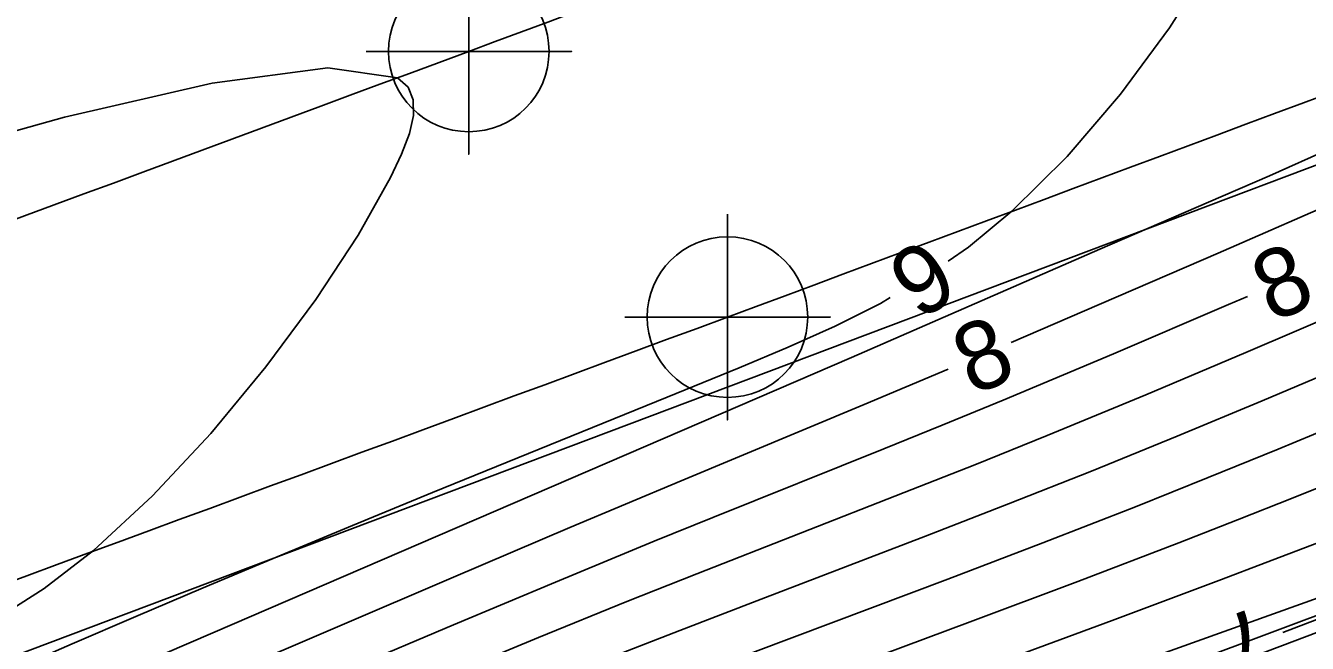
# Model space of a CAD drawing. Extents: x 2602990 to 2605851, y 618069 to 619180.
# Drawn here: x 2603377.87 to 2603415.29, y 618421.79 to 618439.82 of the extents above; entities that cross this region are included whole.
import ezdxf

# ---------------------------------------------------------------- set-up
doc = ezdxf.new("R2010")
doc.units = 0
for name, color, linetype in [('DTM Contours Major', 7, 'Continuous'), ('DTM Contours Major Text', 7, 'Continuous'), ('DTM Contours Minor', 7, 'Continuous'), ('DTM Contours Minor Text', 7, 'Continuous'), ('Exist DTM Breakline', 7, 'Continuous'), ('Exist DTM Crownline', 7, 'Continuous'), ('Exist DTM Crownline Cogo Point CELL', 7, 'Continuous'), ('Exist DTM Drainline', 7, 'Continuous'), ('Exist Roads EOP', 7, 'Continuous'), ('Exist Roads EOP Cogo Point CELL', 7, 'Continuous')]:
    doc.layers.add(name, color=color, linetype=linetype)

# ---------------------------------------------------------------- blocks, each defined once
blk = doc.blocks.new('EXIST DTM CROWNLINE COGO POINT')
at = {"layer": 'Exist DTM Crownline Cogo Point CELL'}
blk.add_lwpolyline([(0, 0.06), (0, -0.06), (0, 0), (0.06, 0), (-0.06, 0)], dxfattribs=at)
blk.add_circle((0, 0), 0.04688, dxfattribs=at)
blk = doc.blocks.new('EXIST ROADS EOP COGO POINT')
at = {"layer": 'Exist Roads EOP Cogo Point CELL'}
blk.add_lwpolyline([(0, 0.06), (0, -0.06), (0, 0), (0.06, 0), (-0.06, 0)], dxfattribs=at)
blk.add_circle((0, 0), 0.04688, dxfattribs=at)

msp = doc.modelspace()

# ---------------------------------------------------------------- linework, layer by layer
at = {"layer": 'DTM Contours Major'}
msp.add_lwpolyline([(2603413.545, 618431.919), (2603412.996, 618431.681), (2603409.631, 618430.243), (2603406.411, 618428.892), (2603404.635, 618428.163), (2603402.929, 618427.472), (2603397.939, 618425.471), (2603396.224, 618424.775), (2603393.341, 618423.584), (2603390.362, 618422.333), (2603387.382, 618421.067), (2603378.36, 618417.204), (2603374.888, 618415.735), (2603371.983, 618414.523), (2603369.421, 618413.467), (2603366.184, 618412.15), (2603362.493, 618410.666), (2603360.498, 618409.871), (2603355.313, 618407.823), (2603347.349, 618404.69), (2603343.063, 618402.99), (2603334.617, 618399.609), (2603327.541, 618396.809), (2603322.626, 618394.861)], dxfattribs=at)
at = {"layer": 'DTM Contours Minor'}
for points in [[(2603412.497, 618441.689), (2603411.27, 618439.754), (2603409.841, 618437.822), (2603408.283, 618436.003), (2603406.67, 618434.405), (2603405.399, 618433.355), (2603404.81, 618432.947)], [(2603374.173, 618435.798), (2603379.013, 618437.147), (2603383.32, 618438.14), (2603386.693, 618438.587), (2603388.731, 618438.3), (2603389.043, 618438.023), (2603389.193, 618437.655), (2603389.198, 618437.203), (2603389.078, 618436.671), (2603388.849, 618436.066), (2603388.529, 618435.392), (2603387.578, 618433.71), (2603386.342, 618431.832), (2603384.886, 618429.866), (2603383.277, 618427.918), (2603381.579, 618426.096), (2603379.858, 618424.507), (2603378.413, 618423.398), (2603377, 618422.497)], [(2603415.971, 618436.239), (2603414.184, 618435.441), (2603412.408, 618434.669), (2603410.673, 618433.922), (2603409.232, 618433.298), (2603401.988, 618430.14), (2603383.339, 618422.102), (2603375.419, 618418.701), (2603372.067, 618417.276), (2603370.458, 618416.602), (2603368.309, 618415.722), (2603367.778, 618415.509)], [(2603416.609, 618434.897), (2603412.686, 618433.182), (2603408.792, 618431.495), (2603406.645, 618430.577)], [(2603403.118, 618431.883), (2603402.833, 618431.716), (2603401.509, 618431.051), (2603400.138, 618430.437), (2603398.705, 618429.837), (2603396.601, 618428.974), (2603389.756, 618426.194), (2603387.413, 618425.235), (2603385.098, 618424.275), (2603383.059, 618423.417), (2603381.096, 618422.58), (2603379.234, 618421.777), (2603375.917, 618420.331), (2603372.342, 618418.768), (2603370.744, 618418.086), (2603369.125, 618417.415), (2603367.476, 618416.749), (2603366.161, 618416.225), (2603363.212, 618415.062), (2603355.846, 618412.179), (2603342.883, 618407.119), (2603323.073, 618399.352)], [(2603420.925, 618431.813), (2603413.975, 618428.875), (2603411.497, 618427.843), (2603408.988, 618426.821), (2603406.566, 618425.862), (2603404.148, 618424.925), (2603399.344, 618423.088), (2603396.97, 618422.174), (2603394.622, 618421.253), (2603392.343, 618420.337), (2603390.114, 618419.421), (2603387.951, 618418.517), (2603383.898, 618416.8), (2603380.805, 618415.486), (2603377.358, 618414.039)], [(2603416.391, 618431.52), (2603413.497, 618430.282), (2603410.574, 618429.047), (2603407.701, 618427.859), (2603405.585, 618427.007), (2603403.524, 618426.193), (2603397.47, 618423.827), (2603395.427, 618423.014), (2603392.846, 618421.963), (2603390.247, 618420.883), (2603387.683, 618419.802), (2603382.87, 618417.749), (2603379.648, 618416.374)], [(2603404.805, 618429.792), (2603402.356, 618428.763), (2603397.015, 618426.54), (2603393.763, 618425.171), (2603390.363, 618423.726), (2603383.658, 618420.855), (2603377.118, 618418.051), (2603373.608, 618416.562), (2603370.947, 618415.449), (2603368.133, 618414.295), (2603365.49, 618413.229), (2603362.398, 618411.996), (2603356.695, 618409.75), (2603347.476, 618406.133), (2603343.027, 618404.375), (2603335.553, 618401.401), (2603324.512, 618397.047), (2603321.717, 618395.941)], [(2603420.115, 618429.811), (2603414.444, 618427.466), (2603412.4, 618426.631), (2603410.273, 618425.78), (2603407.575, 618424.729), (2603404.796, 618423.669), (2603399.182, 618421.553), (2603396.445, 618420.513), (2603393.816, 618419.495), (2603391.861, 618418.719), (2603389.996, 618417.962), (2603388.217, 618417.228), (2603384.894, 618415.834), (2603380.738, 618414.085), (2603376.915, 618412.495), (2603372.47, 618410.663), (2603366.926, 618408.396), (2603360.741, 618405.884), (2603357.67, 618404.644), (2603353.114, 618402.816), (2603345.544, 618399.793), (2603340.999, 618397.957), (2603339.355, 618397.29)], [(2603419.344, 618427.828), (2603414.878, 618426.042), (2603413.257, 618425.399), (2603411.538, 618424.727), (2603408.592, 618423.6), (2603405.452, 618422.42), (2603399.003, 618420.016), (2603395.902, 618418.85), (2603393.023, 618417.746), (2603391.418, 618417.117), (2603389.917, 618416.517), (2603388.501, 618415.943), (2603385.862, 618414.853), (2603379.015, 618412.007), (2603373.646, 618409.794), (2603366.67, 618406.942), (2603359.531, 618404.041), (2603352.87, 618401.348), (2603345.847, 618398.525), (2603340.928, 618396.532), (2603333.274, 618393.41), (2603325.868, 618390.375), (2603313.612, 618385.304)], [(2603417.517, 618425.453), (2603414.066, 618424.14), (2603412.789, 618423.658), (2603409.595, 618422.466), (2603398.796, 618418.475), (2603395.337, 618417.183), (2603392.219, 618416), (2603391, 618415.528), (2603388.789, 618414.656), (2603386.781, 618413.846), (2603382.843, 618412.232), (2603374.157, 618408.651), (2603367.059, 618405.748), (2603358.865, 618402.415), (2603348.621, 618398.269), (2603338.121, 618394.025), (2603335.008, 618392.758), (2603332.478, 618391.718), (2603330.78, 618391.004), (2603330.166, 618390.713), (2603330.794, 618390.91), (2603332.502, 618391.528), (2603335.058, 618392.477), (2603340.472, 618394.503)], [(2603342.346, 618395.203), (2603346.74, 618396.847), (2603349.221, 618397.769), (2603353.79, 618399.451), (2603358.304, 618401.098), (2603362.673, 618402.68), (2603366.805, 618404.166), (2603373.987, 618406.733), (2603380.77, 618409.151), (2603385.418, 618410.826), (2603388.674, 618412.017), (2603392.382, 618413.39), (2603399.188, 618415.936), (2603411.378, 618420.524), (2603420.72, 618424.055)], [(2603419.827, 618424.112), (2603414.576, 618422.113)], [(2603372.825, 618406.789), (2603380.927, 618410.103), (2603382.815, 618410.87), (2603384.744, 618411.647), (2603387.406, 618412.706), (2603389.571, 618413.553), (2603391.107, 618414.144), (2603394.692, 618415.5), (2603398.618, 618416.96), (2603402.718, 618418.467), (2603406.825, 618419.962), (2603410.772, 618421.387), (2603416.399, 618423.403)]]:
    msp.add_lwpolyline(points, dxfattribs=at)
at = {"layer": 'Exist DTM Breakline'}
msp.add_lwpolyline([(2603537.954, 618480.779), (2603486.109, 618461.906), (2603428.704, 618440.722), (2603369.241, 618418.295), (2603303.922, 618394.289), (2603246.763, 618372.687), (2603198.271, 618355.074)], dxfattribs=at)
at = {"layer": 'Exist DTM Crownline'}
msp.add_spline([(2603233.488, 618380.754), (2603285.185, 618400.095), (2603335.457, 618418.629), (2603390.812, 618439.069), (2603440.087, 618457.325), (2603493.996, 618477.231), (2603542.655, 618495.301), (2603600.808, 618516.867), (2603653.659, 618536.362), (2603706.222, 618555.742), (2603764.811, 618577.593), (2603823.52, 618599.847), (2603878.564, 618620.56), (2603937.951, 618643.078), (2603997.369, 618665.789), (2604036.209, 618680.665), (2604055.311, 618688.017)], degree=3, dxfattribs=at)
at = {"layer": 'Exist DTM Drainline'}
msp.add_lwpolyline([(2603204.098, 618342.063), (2603247.886, 618359.31), (2603300.002, 618379.256), (2603348.063, 618397.511), (2603388.725, 618412.554), (2603432.793, 618429.056), (2603474.09, 618444.074), (2603510.151, 618459.891), (2603545.952, 618474.924)], dxfattribs=at)
at = {"layer": 'Exist Roads EOP'}
for points in [[(2603230.17, 618389.98), (2603282.929, 618409.597), (2603332.773, 618427.868), (2603388.167, 618448.413), (2603437.203, 618466.721), (2603490.778, 618486.527), (2603539.039, 618504.558), (2603597.451, 618526.156), (2603651.053, 618545.972), (2603705.208, 618566.084), (2603762.02, 618587.183), (2603820.334, 618609.162), (2603876.341, 618629.99), (2603934.909, 618652.28), (2603996.409, 618675.568), (2604033.216, 618689.957), (2604052.01, 618697.199)], [(2604034.633, 618668.486), (2603984.89, 618650.123), (2603936.767, 618631.654), (2603888.195, 618613.335), (2603837.766, 618594.258), (2603782.918, 618573.705), (2603731.939, 618554.39), (2603671.126, 618532.171), (2603621.822, 618514.106), (2603561.545, 618491.877), (2603506.421, 618471.293), (2603452.163, 618451.33), (2603398.364, 618431.316), (2603341.431, 618410.355), (2603281.65, 618388.199), (2603223.033, 618366.475), (2603185.717, 618352.612)]]:
    msp.add_spline(points, degree=3, dxfattribs=at)

# ---------------------------------------------------------------- block references
at = {"layer": 'Exist DTM Crownline Cogo Point CELL', "xscale": 50, "yscale": 50}
msp.add_blockref('EXIST DTM CROWNLINE COGO POINT', (2603390.812, 618439.069), dxfattribs=at)
at = {"layer": 'Exist Roads EOP Cogo Point CELL', "xscale": 50, "yscale": 50}
msp.add_blockref('EXIST ROADS EOP COGO POINT', (2603398.364, 618431.316), dxfattribs=at)

# ---------------------------------------------------------------- texts
at = {"layer": 'DTM Contours Major Text'}
msp.add_text('8', height=2, rotation=23.3905, dxfattribs=at).set_placement((2603414.26, 618431.139))
at = {"layer": 'DTM Contours Minor Text'}
for s, rotation, p in [('9', 32.1565, (2603403.961, 618431.193)), ('8', 23.0878, (2603405.517, 618429.007)), ('7', 200.8436, (2603413.897, 618422.925))]:
    msp.add_text(s, height=2, rotation=rotation, dxfattribs=at).set_placement(p)

doc.saveas('drawing.dxf')
